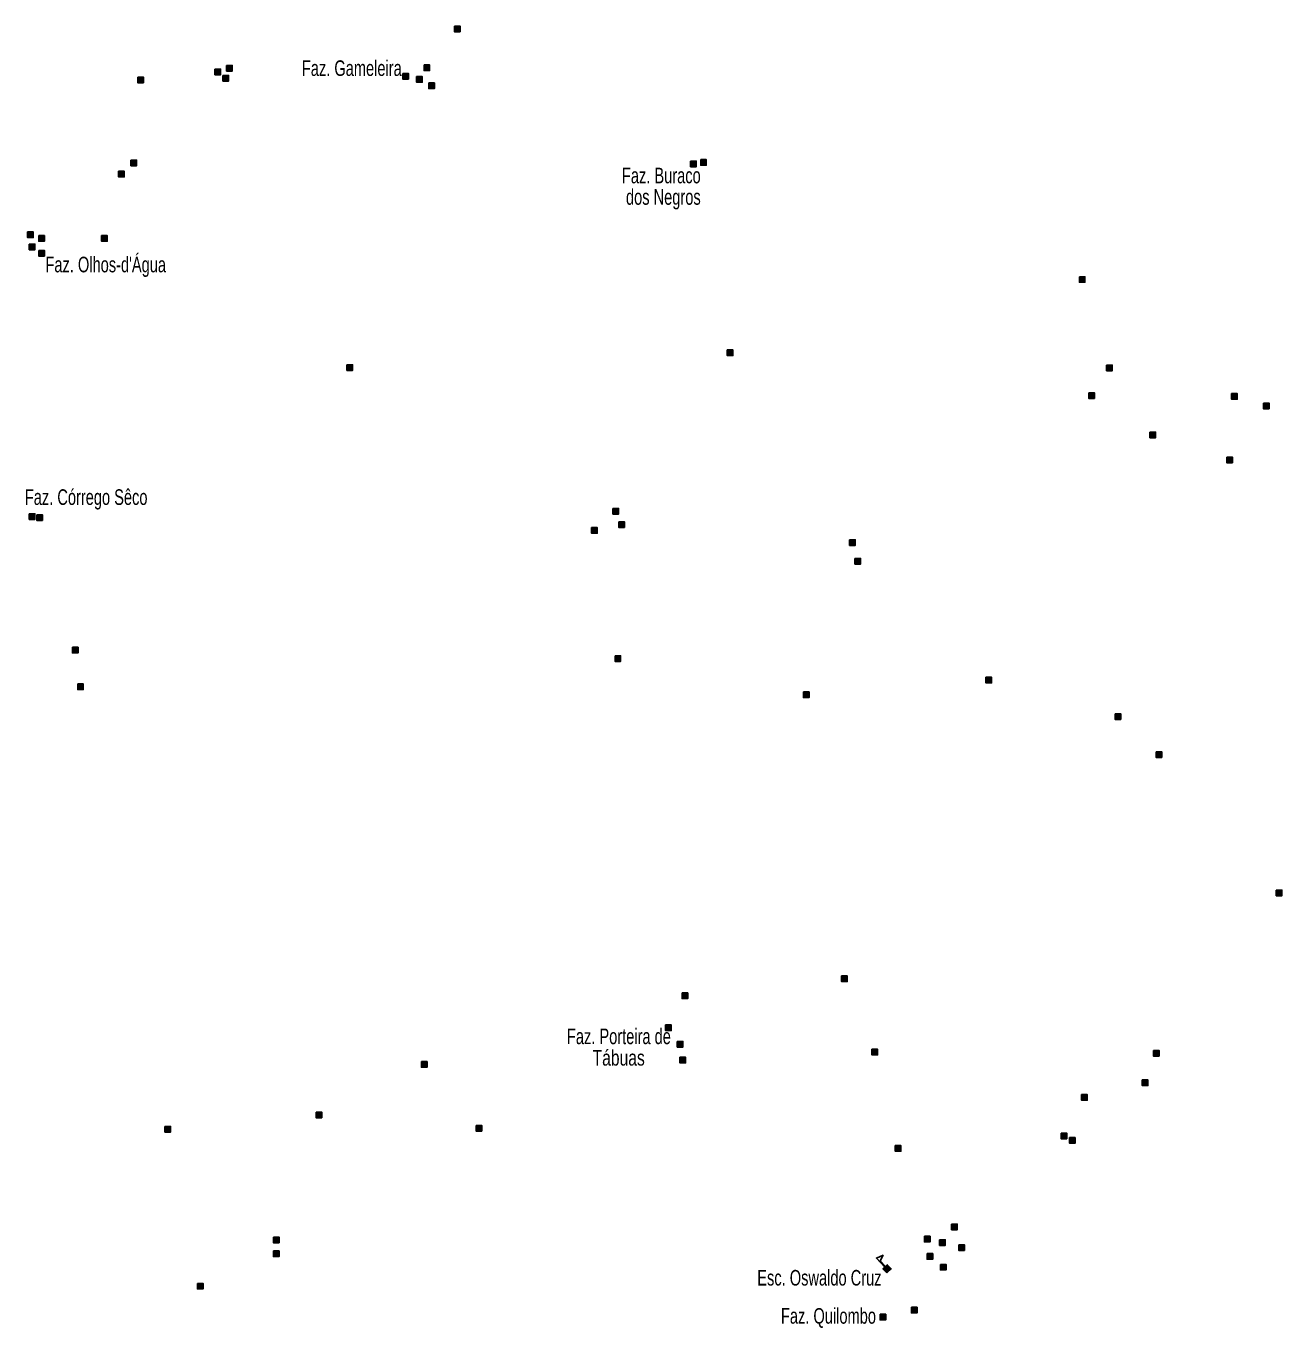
# Model space of a CAD drawing. Extents: x 447.8 to 473.9, y 7733.1 to 7760.8.
# Drawn here: x 447.86 to 454.3, y 7740.03 to 7746.7 of the extents above; entities that cross this region are included whole.
import ezdxf
from ezdxf.enums import TextEntityAlignment as Align

# ---------------------------------------------------------------- set-up
doc = ezdxf.new("R2010")
doc.units = 0
doc.header["$LTSCALE"] = 0.032
doc.layers.add('2', color=7, linetype='Continuous', lineweight=25)
doc.layers.add('4', color=7, linetype='Continuous', lineweight=25)
doc.layers.add('61', color=7, linetype='Continuous')

msp = doc.modelspace()

# ---------------------------------------------------------------- hatches: boundary and pattern name
at = {"layer": '2'}
for points in [[(450.0591, 7746.7048), (450.0881, 7746.7048), (450.0881, 7746.6758), (450.0591, 7746.6758)], [(448.8322, 7746.484), (448.8612, 7746.484), (448.8612, 7746.455), (448.8322, 7746.455)], [(448.8922, 7746.5031), (448.9212, 7746.5031), (448.9212, 7746.4741), (448.8922, 7746.4741)], [(449.9036, 7746.5058), (449.9326, 7746.5058), (449.9326, 7746.4768), (449.9036, 7746.4768)], [(448.4368, 7746.4431), (448.4658, 7746.4431), (448.4658, 7746.4141), (448.4368, 7746.4141)], [(448.8731, 7746.4513), (448.9021, 7746.4513), (448.9021, 7746.4223), (448.8731, 7746.4223)], [(449.7946, 7746.4622), (449.8236, 7746.4622), (449.8236, 7746.4332), (449.7946, 7746.4332)], [(449.8655, 7746.4458), (449.8945, 7746.4458), (449.8945, 7746.4168), (449.8655, 7746.4168)], [(449.9282, 7746.4131), (449.9572, 7746.4131), (449.9572, 7746.3841), (449.9282, 7746.3841)], [(448.4014, 7746.0178), (448.4304, 7746.0178), (448.4304, 7745.9888), (448.4014, 7745.9888)], [(451.3214, 7746.0205), (451.3504, 7746.0205), (451.3504, 7745.9915), (451.3214, 7745.9915)], [(448.3387, 7745.9605), (448.3677, 7745.9605), (448.3677, 7745.9315), (448.3387, 7745.9315)], [(451.2696, 7746.0123), (451.2986, 7746.0123), (451.2986, 7745.9833), (451.2696, 7745.9833)], [(447.8725, 7745.6497), (447.9015, 7745.6497), (447.9015, 7745.6207), (447.8725, 7745.6207)], [(447.9297, 7745.6306), (447.9587, 7745.6306), (447.9587, 7745.6016), (447.9297, 7745.6016)], [(448.2514, 7745.6306), (448.2804, 7745.6306), (448.2804, 7745.6016), (448.2514, 7745.6016)], [(447.8807, 7745.587), (447.9097, 7745.587), (447.9097, 7745.558), (447.8807, 7745.558)], [(447.9297, 7745.5543), (447.9587, 7745.5543), (447.9587, 7745.5253), (447.9297, 7745.5253)], [(453.2619, 7745.42), (453.2909, 7745.42), (453.2909, 7745.391), (453.2619, 7745.391)], [(451.4577, 7745.0444), (451.4867, 7745.0444), (451.4867, 7745.0154), (451.4577, 7745.0154)], [(449.5083, 7744.9681), (449.5373, 7744.9681), (449.5373, 7744.9391), (449.5083, 7744.9391)], [(453.4015, 7744.9668), (453.4305, 7744.9668), (453.4305, 7744.9378), (453.4015, 7744.9378)], [(453.3099, 7744.8249), (453.3389, 7744.8249), (453.3389, 7744.7959), (453.3099, 7744.7959)], [(454.0424, 7744.8203), (454.0714, 7744.8203), (454.0714, 7744.7913), (454.0424, 7744.7913)], [(454.2049, 7744.7722), (454.2339, 7744.7722), (454.2339, 7744.7432), (454.2049, 7744.7432)], [(453.6235, 7744.6234), (453.6525, 7744.6234), (453.6525, 7744.5944), (453.6235, 7744.5944)], [(454.0172, 7744.4953), (454.0462, 7744.4953), (454.0462, 7744.4663), (454.0172, 7744.4663)], [(450.8715, 7744.232), (450.9005, 7744.232), (450.9005, 7744.203), (450.8715, 7744.203)], [(447.8807, 7744.2047), (447.9097, 7744.2047), (447.9097, 7744.1757), (447.8807, 7744.1757)], [(447.9188, 7744.1992), (447.9478, 7744.1992), (447.9478, 7744.1702), (447.9188, 7744.1702)], [(450.9015, 7744.1638), (450.9305, 7744.1638), (450.9305, 7744.1348), (450.9015, 7744.1348)], [(450.7625, 7744.1338), (450.7915, 7744.1338), (450.7915, 7744.1048), (450.7625, 7744.1048)], [(452.0848, 7744.0711), (452.1138, 7744.0711), (452.1138, 7744.0421), (452.0848, 7744.0421)], [(452.112, 7743.9757), (452.141, 7743.9757), (452.141, 7743.9467), (452.112, 7743.9467)], [(448.1015, 7743.5204), (448.1305, 7743.5204), (448.1305, 7743.4914), (448.1015, 7743.4914)], [(450.8824, 7743.4767), (450.9114, 7743.4767), (450.9114, 7743.4477), (450.8824, 7743.4477)], [(452.7835, 7743.3669), (452.8125, 7743.3669), (452.8125, 7743.3379), (452.7835, 7743.3379)], [(448.1288, 7743.3322), (448.1578, 7743.3322), (448.1578, 7743.3032), (448.1288, 7743.3032)], [(451.8476, 7743.2914), (451.8766, 7743.2914), (451.8766, 7743.2624), (451.8476, 7743.2624)], [(453.445, 7743.1792), (453.474, 7743.1792), (453.474, 7743.1502), (453.445, 7743.1502)], [(453.6555, 7742.9846), (453.6845, 7742.9846), (453.6845, 7742.9556), (453.6555, 7742.9556)], [(454.2712, 7742.2751), (454.3002, 7742.2751), (454.3002, 7742.2461), (454.2712, 7742.2461)], [(452.0439, 7741.8354), (452.0729, 7741.8354), (452.0729, 7741.8064), (452.0439, 7741.8064)], [(451.226, 7741.7482), (451.255, 7741.7482), (451.255, 7741.7192), (451.226, 7741.7192)], [(451.1414, 7741.5846), (451.1704, 7741.5846), (451.1704, 7741.5556), (451.1414, 7741.5556)], [(451.2014, 7741.5001), (451.2304, 7741.5001), (451.2304, 7741.4711), (451.2014, 7741.4711)], [(451.2151, 7741.4183), (451.2441, 7741.4183), (451.2441, 7741.3893), (451.2151, 7741.3893)], [(452.1993, 7741.4592), (452.2283, 7741.4592), (452.2283, 7741.4302), (452.1993, 7741.4302)], [(453.6418, 7741.4534), (453.6708, 7741.4534), (453.6708, 7741.4244), (453.6418, 7741.4244)], [(449.89, 7741.3965), (449.919, 7741.3965), (449.919, 7741.3675), (449.89, 7741.3675)], [(453.5846, 7741.3023), (453.6136, 7741.3023), (453.6136, 7741.2733), (453.5846, 7741.2733)], [(453.2733, 7741.2268), (453.3023, 7741.2268), (453.3023, 7741.1978), (453.2733, 7741.1978)], [(449.3502, 7741.1375), (449.3792, 7741.1375), (449.3792, 7741.1085), (449.3502, 7741.1085)], [(448.5759, 7741.0639), (448.6049, 7741.0639), (448.6049, 7741.0349), (448.5759, 7741.0349)], [(450.1708, 7741.0693), (450.1998, 7741.0693), (450.1998, 7741.0403), (450.1708, 7741.0403)], [(453.168, 7741.0299), (453.197, 7741.0299), (453.197, 7741.0009), (453.168, 7741.0009)], [(452.3188, 7740.9658), (452.3478, 7740.9658), (452.3478, 7740.9368), (452.3188, 7740.9368)], [(453.2115, 7741.007), (453.2405, 7741.007), (453.2405, 7740.978), (453.2115, 7740.978)], [(452.6072, 7740.563), (452.6362, 7740.563), (452.6362, 7740.534), (452.6072, 7740.534)], [(449.1321, 7740.4968), (449.1611, 7740.4968), (449.1611, 7740.4678), (449.1321, 7740.4678)], [(452.4676, 7740.5012), (452.4966, 7740.5012), (452.4966, 7740.4722), (452.4676, 7740.4722)], [(452.5454, 7740.4829), (452.5744, 7740.4829), (452.5744, 7740.4539), (452.5454, 7740.4539)], [(449.1321, 7740.4259), (449.1611, 7740.4259), (449.1611, 7740.3969), (449.1321, 7740.3969)], [(452.4814, 7740.4119), (452.5104, 7740.4119), (452.5104, 7740.3829), (452.4814, 7740.3829)], [(452.6439, 7740.4577), (452.6729, 7740.4577), (452.6729, 7740.4287), (452.6439, 7740.4287)], [(452.55, 7740.357), (452.579, 7740.357), (452.579, 7740.328), (452.55, 7740.328)], [(448.7422, 7740.2596), (448.7712, 7740.2596), (448.7712, 7740.2306), (448.7422, 7740.2306)], [(452.241, 7740.1007), (452.27, 7740.1007), (452.27, 7740.0717), (452.241, 7740.0717)], [(452.4012, 7740.1373), (452.4302, 7740.1373), (452.4302, 7740.1083), (452.4012, 7740.1083)]]:
    msp.add_hatch(color=256, dxfattribs=at).paths.add_polyline_path(points)
at = {"layer": '4'}
msp.add_hatch(color=256, dxfattribs=at).paths.add_polyline_path([(452.2759, 7740.3127), (452.2554, 7740.3346), (452.2773, 7740.3551), (452.2978, 7740.3332)])

# ---------------------------------------------------------------- linework, layer by layer
at = {"layer": '2'}
for points in [[(450.0591, 7746.7048), (450.0881, 7746.7048), (450.0881, 7746.6758), (450.0591, 7746.6758)], [(448.8322, 7746.484), (448.8612, 7746.484), (448.8612, 7746.455), (448.8322, 7746.455)], [(448.8922, 7746.5031), (448.9212, 7746.5031), (448.9212, 7746.4741), (448.8922, 7746.4741)], [(449.9036, 7746.5058), (449.9326, 7746.5058), (449.9326, 7746.4768), (449.9036, 7746.4768)], [(448.4368, 7746.4431), (448.4658, 7746.4431), (448.4658, 7746.4141), (448.4368, 7746.4141)], [(448.8731, 7746.4513), (448.9021, 7746.4513), (448.9021, 7746.4223), (448.8731, 7746.4223)], [(449.7946, 7746.4622), (449.8236, 7746.4622), (449.8236, 7746.4332), (449.7946, 7746.4332)], [(449.8655, 7746.4458), (449.8945, 7746.4458), (449.8945, 7746.4168), (449.8655, 7746.4168)], [(449.9282, 7746.4131), (449.9572, 7746.4131), (449.9572, 7746.3841), (449.9282, 7746.3841)], [(448.4014, 7746.0178), (448.4304, 7746.0178), (448.4304, 7745.9888), (448.4014, 7745.9888)], [(451.3214, 7746.0205), (451.3504, 7746.0205), (451.3504, 7745.9915), (451.3214, 7745.9915)], [(448.3387, 7745.9605), (448.3677, 7745.9605), (448.3677, 7745.9315), (448.3387, 7745.9315)], [(451.2696, 7746.0123), (451.2986, 7746.0123), (451.2986, 7745.9833), (451.2696, 7745.9833)], [(447.8725, 7745.6497), (447.9015, 7745.6497), (447.9015, 7745.6207), (447.8725, 7745.6207)], [(447.9297, 7745.6306), (447.9587, 7745.6306), (447.9587, 7745.6016), (447.9297, 7745.6016)], [(448.2514, 7745.6306), (448.2804, 7745.6306), (448.2804, 7745.6016), (448.2514, 7745.6016)], [(447.8807, 7745.587), (447.9097, 7745.587), (447.9097, 7745.558), (447.8807, 7745.558)], [(447.9297, 7745.5543), (447.9587, 7745.5543), (447.9587, 7745.5253), (447.9297, 7745.5253)], [(453.2619, 7745.42), (453.2909, 7745.42), (453.2909, 7745.391), (453.2619, 7745.391)], [(451.4577, 7745.0444), (451.4867, 7745.0444), (451.4867, 7745.0154), (451.4577, 7745.0154)], [(449.5083, 7744.9681), (449.5373, 7744.9681), (449.5373, 7744.9391), (449.5083, 7744.9391)], [(453.4015, 7744.9668), (453.4305, 7744.9668), (453.4305, 7744.9378), (453.4015, 7744.9378)], [(453.3099, 7744.8249), (453.3389, 7744.8249), (453.3389, 7744.7959), (453.3099, 7744.7959)], [(454.0424, 7744.8203), (454.0714, 7744.8203), (454.0714, 7744.7913), (454.0424, 7744.7913)], [(454.2049, 7744.7722), (454.2339, 7744.7722), (454.2339, 7744.7432), (454.2049, 7744.7432)], [(453.6235, 7744.6234), (453.6525, 7744.6234), (453.6525, 7744.5944), (453.6235, 7744.5944)], [(454.0172, 7744.4953), (454.0462, 7744.4953), (454.0462, 7744.4663), (454.0172, 7744.4663)], [(450.8715, 7744.232), (450.9005, 7744.232), (450.9005, 7744.203), (450.8715, 7744.203)], [(447.8807, 7744.2047), (447.9097, 7744.2047), (447.9097, 7744.1757), (447.8807, 7744.1757)], [(447.9188, 7744.1992), (447.9478, 7744.1992), (447.9478, 7744.1702), (447.9188, 7744.1702)], [(450.9015, 7744.1638), (450.9305, 7744.1638), (450.9305, 7744.1348), (450.9015, 7744.1348)], [(450.7625, 7744.1338), (450.7915, 7744.1338), (450.7915, 7744.1048), (450.7625, 7744.1048)], [(452.0848, 7744.0711), (452.1138, 7744.0711), (452.1138, 7744.0421), (452.0848, 7744.0421)], [(452.112, 7743.9757), (452.141, 7743.9757), (452.141, 7743.9467), (452.112, 7743.9467)], [(448.1015, 7743.5204), (448.1305, 7743.5204), (448.1305, 7743.4914), (448.1015, 7743.4914)], [(450.8824, 7743.4767), (450.9114, 7743.4767), (450.9114, 7743.4477), (450.8824, 7743.4477)], [(452.7835, 7743.3669), (452.8125, 7743.3669), (452.8125, 7743.3379), (452.7835, 7743.3379)], [(448.1288, 7743.3322), (448.1578, 7743.3322), (448.1578, 7743.3032), (448.1288, 7743.3032)], [(451.8476, 7743.2914), (451.8766, 7743.2914), (451.8766, 7743.2624), (451.8476, 7743.2624)], [(453.445, 7743.1792), (453.474, 7743.1792), (453.474, 7743.1502), (453.445, 7743.1502)], [(453.6555, 7742.9846), (453.6845, 7742.9846), (453.6845, 7742.9556), (453.6555, 7742.9556)], [(454.2712, 7742.2751), (454.3002, 7742.2751), (454.3002, 7742.2461), (454.2712, 7742.2461)], [(452.0439, 7741.8354), (452.0729, 7741.8354), (452.0729, 7741.8064), (452.0439, 7741.8064)], [(451.226, 7741.7482), (451.255, 7741.7482), (451.255, 7741.7192), (451.226, 7741.7192)], [(451.1414, 7741.5846), (451.1704, 7741.5846), (451.1704, 7741.5556), (451.1414, 7741.5556)], [(451.2014, 7741.5001), (451.2304, 7741.5001), (451.2304, 7741.4711), (451.2014, 7741.4711)], [(451.2151, 7741.4183), (451.2441, 7741.4183), (451.2441, 7741.3893), (451.2151, 7741.3893)], [(452.1993, 7741.4592), (452.2283, 7741.4592), (452.2283, 7741.4302), (452.1993, 7741.4302)], [(453.6418, 7741.4534), (453.6708, 7741.4534), (453.6708, 7741.4244), (453.6418, 7741.4244)], [(449.89, 7741.3965), (449.919, 7741.3965), (449.919, 7741.3675), (449.89, 7741.3675)], [(453.5846, 7741.3023), (453.6136, 7741.3023), (453.6136, 7741.2733), (453.5846, 7741.2733)], [(453.2733, 7741.2268), (453.3023, 7741.2268), (453.3023, 7741.1978), (453.2733, 7741.1978)], [(449.3502, 7741.1375), (449.3792, 7741.1375), (449.3792, 7741.1085), (449.3502, 7741.1085)], [(448.5759, 7741.0639), (448.6049, 7741.0639), (448.6049, 7741.0349), (448.5759, 7741.0349)], [(450.1708, 7741.0693), (450.1998, 7741.0693), (450.1998, 7741.0403), (450.1708, 7741.0403)], [(453.168, 7741.0299), (453.197, 7741.0299), (453.197, 7741.0009), (453.168, 7741.0009)], [(452.3188, 7740.9658), (452.3478, 7740.9658), (452.3478, 7740.9368), (452.3188, 7740.9368)], [(453.2115, 7741.007), (453.2405, 7741.007), (453.2405, 7740.978), (453.2115, 7740.978)], [(452.6072, 7740.563), (452.6362, 7740.563), (452.6362, 7740.534), (452.6072, 7740.534)], [(449.1321, 7740.4968), (449.1611, 7740.4968), (449.1611, 7740.4678), (449.1321, 7740.4678)], [(452.4676, 7740.5012), (452.4966, 7740.5012), (452.4966, 7740.4722), (452.4676, 7740.4722)], [(452.5454, 7740.4829), (452.5744, 7740.4829), (452.5744, 7740.4539), (452.5454, 7740.4539)], [(449.1321, 7740.4259), (449.1611, 7740.4259), (449.1611, 7740.3969), (449.1321, 7740.3969)], [(452.4814, 7740.4119), (452.5104, 7740.4119), (452.5104, 7740.3829), (452.4814, 7740.3829)], [(452.6439, 7740.4577), (452.6729, 7740.4577), (452.6729, 7740.4287), (452.6439, 7740.4287)], [(452.55, 7740.357), (452.579, 7740.357), (452.579, 7740.328), (452.55, 7740.328)], [(448.7422, 7740.2596), (448.7712, 7740.2596), (448.7712, 7740.2306), (448.7422, 7740.2306)], [(452.241, 7740.1007), (452.27, 7740.1007), (452.27, 7740.0717), (452.241, 7740.0717)], [(452.4012, 7740.1373), (452.4302, 7740.1373), (452.4302, 7740.1083), (452.4012, 7740.1083)]]:
    msp.add_lwpolyline(points, close=True, dxfattribs=at)
at = {"layer": '4'}
msp.add_line((452.2645, 7740.3431), (452.2682, 7740.3466), dxfattribs=at)
for points in [[(452.2645, 7740.3431), (452.2218, 7740.3888), (452.2559, 7740.4036), (452.2412, 7740.3754), (452.2682, 7740.3466)], [(452.2759, 7740.3127), (452.2554, 7740.3346), (452.2773, 7740.3551), (452.2978, 7740.3332)]]:
    msp.add_lwpolyline(points, close=True, dxfattribs=at)

# ---------------------------------------------------------------- texts
at = {"layer": '61'}
for s, width, p in [('Faz. Gameleira', 0.7, (449.7896, 7746.449)), ('Faz. Buraco', 0.7, (451.3216, 7745.8986)), (' dos Negros', 0.7, (451.3216, 7745.7886)), ('Faz. Porteira de', 0.7, (451.1688, 7741.4857)), ('       Tábuas      ', 0.75, (451.1688, 7741.3757)), ('Esc. Oswaldo Cruz', 0.7, (452.2482, 7740.2482)), ('Faz. Quilombo', 0.7, (452.2197, 7740.0528))]:
    msp.add_text(s, height=0.08, dxfattribs=dict(at, width=width)).set_placement(p, align=Align.RIGHT)
at = {"layer": '61', "width": 0.7}
for s, p in [("Faz. Olhos-d'Água", (447.9637, 7745.4423)), ('Faz. Córrego Sêco', (447.8581, 7744.25))]:
    msp.add_text(s, height=0.08, dxfattribs=at).set_placement(p)

doc.saveas('drawing.dxf')
